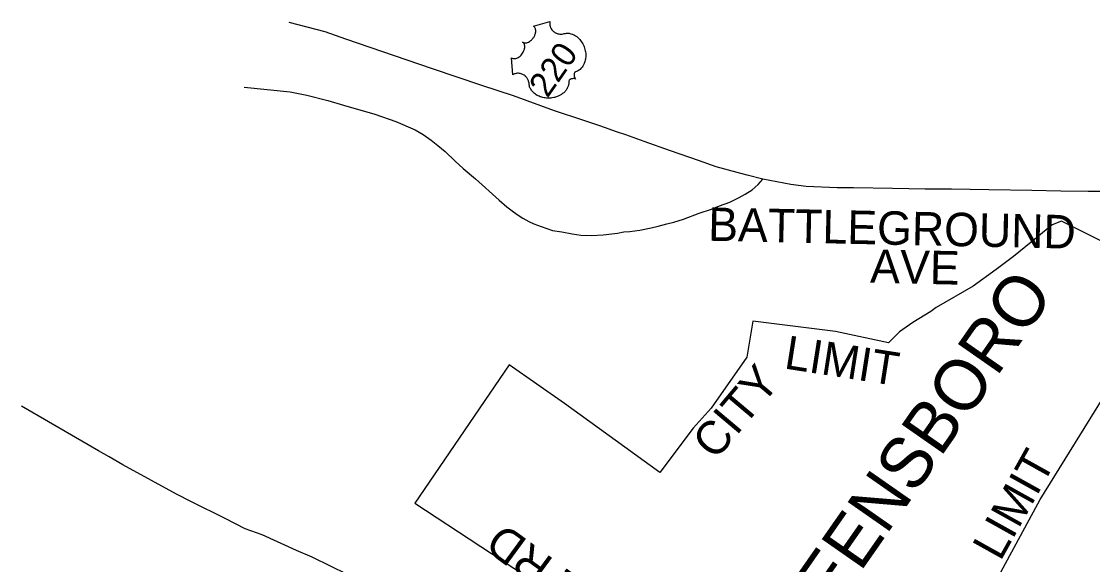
# Model space of a CAD drawing. Extents: x 1731327 to 1735374, y 884856 to 889832.
# Drawn here: x 1731417.3 to 1731582.7, y 885424.2 to 885508.1 of the extents above; entities that cross this region are included whole.
import ezdxf

# ---------------------------------------------------------------- set-up
doc = ezdxf.new("R2010")
doc.units = 0
for name, color, linetype in [('CTL Bench Mark CELL', 7, 'Continuous'), ('Exist Other Culture Located Object CELL', 7, 'Continuous'), ('Exist Other Culture Sign Text', 7, 'Continuous'), ('Exist Roads EOP Other Text', 7, 'Continuous'), ('Exist Roads EOP Text', 7, 'Continuous'), ('Exist Structure Major Deck Tunnel Box Culvert Text', 7, 'Continuous')]:
    doc.layers.add(name, color=color, linetype=linetype)

msp = doc.modelspace()

# ---------------------------------------------------------------- linework, layer by layer
at = {"layer": 'Exist Other Culture Located Object CELL'}
for points in [[(1731451.7, 885497.93), (1731458.83, 885497.21), (1731461.36, 885496.72), (1731464.62, 885495.89), (1731467.05, 885495.19), (1731471.9, 885493.78), (1731475.15, 885492.62), (1731478.1, 885491.36), (1731479.34, 885490.63), (1731480.59, 885489.77), (1731481.62, 885488.93), (1731482.74, 885487.99), (1731484.31, 885486.51)], [(1731484.31, 885486.51), (1731485.53, 885485.36), (1731487.42, 885483.77), (1731491.09, 885480.47), (1731492.28, 885479.45), (1731493.1, 885478.83), (1731493.87, 885478.28), (1731494.74, 885477.7), (1731495.69, 885477.2), (1731496.42, 885476.86), (1731497.57, 885476.4), (1731499.34, 885475.81), (1731500.77, 885475.58), (1731502.39, 885475.27), (1731503.68, 885475.08), (1731505.37, 885475.02), (1731507.16, 885475.15), (1731509.35, 885475.38), (1731510.36, 885475.58), (1731511.27, 885475.64), (1731512.81, 885475.87), (1731514.56, 885476.2), (1731515.67, 885476.47), (1731516.98, 885476.83), (1731518.09, 885477.11), (1731519.55, 885477.58), (1731521.98, 885478.49), (1731523.86, 885479.11), (1731525.1, 885479.62), (1731526.7, 885480.21), (1731528.18, 885480.88), (1731529.07, 885481.41), (1731530.14, 885482.08), (1731531.09, 885482.92), (1731531.83, 885483.76)], [(1731476.24, 885417.55), (1731472.57, 885419.98), (1731470.96, 885420.95), (1731469.44, 885421.77), (1731467.47, 885422.77), (1731465.14, 885423.93), (1731462.23, 885425.37), (1731459.79, 885426.39), (1731454.47, 885428.81), (1731451.85, 885429.73), (1731448.76, 885431.3), (1731443.57, 885433.89), (1731441.26, 885435.08), (1731437.37, 885437.2), (1731432.96, 885439.62), (1731430.84, 885440.83), (1731429.21, 885441.78), (1731417.3, 885448.65)]]:
    msp.add_lwpolyline(points, dxfattribs=at)
at = {"layer": 'Exist Other Culture Sign Text'}
for points in [[(1731585.56, 885473.42), (1731577.93, 885477.27), (1731576.52, 885476.67), (1731574.09, 885474.69), (1731570.52, 885471.77), (1731567.85, 885469.77), (1731564.28, 885467.19), (1731558.57, 885463.91), (1731557.76, 885463.3), (1731554.99, 885461.58), (1731552.93, 885460.13), (1731551.22, 885458.44), (1731543.04, 885460.22), (1731530.27, 885461.8), (1731529.35, 885456.25), (1731523.84, 885448.36), (1731521.03, 885445.29), (1731515.92, 885438.45), (1731501.19, 885449.07), (1731492.61, 885455.05), (1731478.04, 885433.68), (1731501.75, 885418.14)], [(1731436.56, 885269.4), (1731438.83, 885274.8), (1731441.07, 885273.73), (1731448, 885279.37), (1731458.75, 885273.36), (1731465.04, 885280.94), (1731460.35, 885284.21), (1731467.7, 885294.03), (1731466.12, 885347.48), (1731483.94, 885369.44), (1731489.63, 885375.45), (1731502.31, 885385.05), (1731500.42, 885387.96), (1731512.4, 885394.83), (1731516.87, 885391.9), (1731529.38, 885403.84), (1731536.47, 885399.16), (1731545.02, 885404.34), (1731554.34, 885410.44), (1731561.05, 885415.18), (1731565.57, 885417.53), (1731574.63, 885434.26), (1731585.3, 885451.43)]]:
    msp.add_lwpolyline(points, dxfattribs=at)
at = {"layer": 'Exist Roads EOP Other Text'}
for points in [[(1731504.02, 885492.85), (1731499.66, 885494.27), (1731493.29, 885496.6), (1731488.42, 885498.21), (1731480.78, 885500.78), (1731474.93, 885502.8), (1731467.42, 885505.34), (1731464.24, 885506.5), (1731458.67, 885507.93)], [(1731531.83, 885483.76), (1731529.38, 885484.36), (1731527.86, 885484.75), (1731524.59, 885485.66), (1731521.89, 885486.61), (1731517.57, 885488.12), (1731513.47, 885489.56), (1731510.65, 885490.58), (1731509.39, 885491), (1731506.65, 885491.96), (1731504.02, 885492.85)], [(1731594.82, 885480.03), (1731590.92, 885480.95), (1731588.57, 885481.48), (1731586.45, 885481.75), (1731584.48, 885481.83), (1731582.05, 885481.85), (1731577.86, 885481.9), (1731573.36, 885482), (1731566.72, 885482.1), (1731560.93, 885482.18), (1731556.89, 885482.2), (1731551.82, 885482.3), (1731545.82, 885482.38), (1731543.29, 885482.41), (1731538.5, 885482.62), (1731536.16, 885482.93), (1731531.83, 885483.76)]]:
    msp.add_lwpolyline(points, dxfattribs=at)
at = {"layer": 'Exist Roads EOP Text'}
for p, q in [((1731496.41, 885507.35), (1731498.94, 885508.1)), ((1731496.46, 885507.31), (1731496.41, 885507.35)), ((1731496.51, 885507.26), (1731496.46, 885507.31)), ((1731496.57, 885507.2), (1731496.51, 885507.26)), ((1731496.61, 885507.13), (1731496.57, 885507.2)), ((1731496.65, 885507.06), (1731496.61, 885507.13)), ((1731496.68, 885506.97), (1731496.65, 885507.06)), ((1731496.72, 885506.85), (1731496.68, 885506.97)), ((1731496.73, 885506.73), (1731496.72, 885506.85)), ((1731498.91, 885507.93), (1731498.9, 885507.83)), ((1731498.9, 885507.83), (1731498.91, 885507.65)), ((1731498.93, 885508.05), (1731498.91, 885507.93)), ((1731498.91, 885507.65), (1731498.92, 885507.57)), ((1731498.92, 885507.57), (1731498.93, 885507.49)), ((1731498.94, 885508.1), (1731498.93, 885508.05)), ((1731498.93, 885507.49), (1731498.95, 885507.41)), ((1731498.95, 885507.41), (1731498.96, 885507.33)), ((1731498.96, 885507.33), (1731499, 885507.24)), ((1731499, 885507.24), (1731499.04, 885507.14)), ((1731499.04, 885507.14), (1731499.08, 885507.05)), ((1731499.08, 885507.05), (1731499.12, 885506.97)), ((1731499.12, 885506.97), (1731499.22, 885506.82)), ((1731499.22, 885506.82), (1731499.29, 885506.74)), ((1731495.91, 885505.08), (1731496, 885505.15)), ((1731496, 885505.15), (1731496.08, 885505.23)), ((1731496.08, 885505.23), (1731496.16, 885505.3)), ((1731496.16, 885505.3), (1731496.23, 885505.39)), ((1731496.23, 885505.39), (1731496.31, 885505.47)), ((1731496.31, 885505.47), (1731496.36, 885505.55)), ((1731496.36, 885505.55), (1731496.42, 885505.64)), ((1731496.42, 885505.64), (1731496.48, 885505.73)), ((1731496.48, 885505.73), (1731496.53, 885505.82)), ((1731496.53, 885505.82), (1731496.58, 885505.93)), ((1731496.58, 885505.93), (1731496.62, 885506.02)), ((1731496.62, 885506.02), (1731496.66, 885506.14)), ((1731496.66, 885506.14), (1731496.69, 885506.26)), ((1731496.69, 885506.26), (1731496.71, 885506.36)), ((1731496.71, 885506.36), (1731496.73, 885506.51)), ((1731496.74, 885506.63), (1731496.73, 885506.73)), ((1731496.73, 885506.51), (1731496.74, 885506.63)), ((1731499.29, 885506.74), (1731499.36, 885506.67)), ((1731499.36, 885506.67), (1731499.49, 885506.55)), ((1731499.49, 885506.55), (1731499.56, 885506.49)), ((1731499.56, 885506.49), (1731499.63, 885506.44)), ((1731499.63, 885506.44), (1731499.71, 885506.39)), ((1731499.71, 885506.39), (1731499.79, 885506.35)), ((1731499.79, 885506.35), (1731499.87, 885506.31)), ((1731499.87, 885506.31), (1731499.95, 885506.28)), ((1731499.95, 885506.28), (1731500.04, 885506.24)), ((1731500.04, 885506.24), (1731500.16, 885506.2)), ((1731500.16, 885506.2), (1731500.28, 885506.18)), ((1731500.28, 885506.18), (1731500.48, 885506.15)), ((1731500.48, 885506.15), (1731500.7, 885506.15)), ((1731500.7, 885506.15), (1731500.83, 885506.16)), ((1731500.83, 885506.16), (1731500.95, 885506.18)), ((1731500.95, 885506.18), (1731501.11, 885506.22)), ((1731501.11, 885506.22), (1731501.2, 885506.24)), ((1731501.2, 885506.24), (1731501.31, 885506.26)), ((1731501.31, 885506.26), (1731501.51, 885506.28)), ((1731501.51, 885506.28), (1731501.6, 885506.29)), ((1731501.6, 885506.29), (1731501.7, 885506.28)), ((1731501.7, 885506.28), (1731501.79, 885506.28)), ((1731501.79, 885506.28), (1731501.89, 885506.27)), ((1731501.89, 885506.27), (1731501.98, 885506.26)), ((1731501.98, 885506.26), (1731502.16, 885506.21)), ((1731502.16, 885506.21), (1731502.34, 885506.16)), ((1731502.34, 885506.16), (1731502.42, 885506.13)), ((1731502.42, 885506.13), (1731502.61, 885506.04)), ((1731502.61, 885506.04), (1731502.7, 885506)), ((1731502.7, 885506), (1731502.88, 885505.9)), ((1731502.88, 885505.9), (1731503.07, 885505.76)), ((1731503.07, 885505.76), (1731503.25, 885505.61)), ((1731503.25, 885505.61), (1731503.44, 885505.43)), ((1731503.44, 885505.43), (1731503.55, 885505.31)), ((1731503.55, 885505.31), (1731503.67, 885505.16)), ((1731503.67, 885505.16), (1731503.77, 885505.02)), ((1731494.8, 885504.85), (1731494.71, 885504.92)), ((1731494.71, 885504.92), (1731494.8, 885504.87)), ((1731494.8, 885504.87), (1731494.85, 885504.84)), ((1731494.84, 885504.81), (1731494.8, 885504.85)), ((1731494.82, 885503.37), (1731494.92, 885503.59)), ((1731494.92, 885504.7), (1731494.84, 885504.81)), ((1731494.85, 885504.84), (1731494.91, 885504.82)), ((1731494.91, 885504.82), (1731494.97, 885504.81)), ((1731494.95, 885504.64), (1731494.92, 885504.7)), ((1731494.92, 885503.59), (1731494.96, 885503.69)), ((1731494.98, 885504.57), (1731494.95, 885504.64)), ((1731494.96, 885503.69), (1731494.99, 885503.82)), ((1731494.97, 885504.81), (1731495.07, 885504.79)), ((1731495.02, 885504.44), (1731494.98, 885504.57)), ((1731494.99, 885503.82), (1731495.02, 885503.94)), ((1731495.04, 885504.29), (1731495.02, 885504.44)), ((1731495.02, 885503.94), (1731495.04, 885504.08)), ((1731495.04, 885504.19), (1731495.04, 885504.29)), ((1731495.04, 885504.08), (1731495.04, 885504.19)), ((1731495.07, 885504.79), (1731495.16, 885504.79)), ((1731495.16, 885504.79), (1731495.3, 885504.8)), ((1731495.3, 885504.8), (1731495.38, 885504.82)), ((1731495.38, 885504.82), (1731495.44, 885504.84)), ((1731495.44, 885504.84), (1731495.6, 885504.9)), ((1731495.6, 885504.9), (1731495.77, 885504.99)), ((1731495.77, 885504.99), (1731495.84, 885505.03)), ((1731495.84, 885505.03), (1731495.91, 885505.08)), ((1731503.77, 885505.02), (1731503.91, 885504.81)), ((1731503.91, 885504.81), (1731504.01, 885504.64)), ((1731504.01, 885504.64), (1731504.11, 885504.44)), ((1731504.11, 885504.44), (1731504.16, 885504.31)), ((1731504.16, 885504.31), (1731504.22, 885504.16)), ((1731504.22, 885504.16), (1731504.28, 885503.99)), ((1731504.28, 885503.99), (1731504.34, 885503.79)), ((1731504.34, 885503.79), (1731504.39, 885503.57)), ((1731504.39, 885503.57), (1731504.42, 885503.4)), ((1731493.19, 885499.84), (1731493.02, 885502.49)), ((1731493.02, 885502.49), (1731493.09, 885502.44)), ((1731493.09, 885502.44), (1731493.19, 885502.4)), ((1731493.19, 885502.4), (1731493.24, 885502.38)), ((1731493.24, 885502.38), (1731493.35, 885502.37)), ((1731493.35, 885502.37), (1731493.49, 885502.36)), ((1731493.49, 885502.36), (1731493.65, 885502.39)), ((1731493.65, 885502.39), (1731493.81, 885502.43)), ((1731493.81, 885502.43), (1731493.9, 885502.47)), ((1731493.9, 885502.47), (1731494.04, 885502.54)), ((1731494.04, 885502.54), (1731494.19, 885502.63)), ((1731494.19, 885502.63), (1731494.33, 885502.75)), ((1731494.33, 885502.75), (1731494.47, 885502.88)), ((1731494.47, 885502.88), (1731494.6, 885503.03)), ((1731494.6, 885503.03), (1731494.71, 885503.19)), ((1731494.71, 885503.19), (1731494.82, 885503.37)), ((1731504.34, 885501.92), (1731504.23, 885501.62)), ((1731504.38, 885502.11), (1731504.34, 885501.92)), ((1731504.41, 885502.26), (1731504.38, 885502.11)), ((1731504.44, 885502.44), (1731504.41, 885502.26)), ((1731504.42, 885503.4), (1731504.45, 885503.18)), ((1731504.46, 885502.65), (1731504.44, 885502.44)), ((1731504.45, 885503.18), (1731504.46, 885503.06)), ((1731504.46, 885503.06), (1731504.46, 885502.88)), ((1731504.46, 885502.88), (1731504.46, 885502.65)), ((1731502.72, 885500.16), (1731502.69, 885500.08)), ((1731502.78, 885500.24), (1731502.72, 885500.16)), ((1731502.82, 885500.27), (1731502.78, 885500.24)), ((1731502.89, 885500.31), (1731502.82, 885500.27)), ((1731503.17, 885500.43), (1731502.89, 885500.31)), ((1731503.32, 885500.51), (1731503.17, 885500.43)), ((1731503.45, 885500.6), (1731503.32, 885500.51)), ((1731503.59, 885500.7), (1731503.45, 885500.6)), ((1731503.7, 885500.81), (1731503.59, 885500.7)), ((1731503.81, 885500.93), (1731503.7, 885500.81)), ((1731503.91, 885501.05), (1731503.81, 885500.93)), ((1731504, 885501.18), (1731503.91, 885501.05)), ((1731504.07, 885501.29), (1731504, 885501.18)), ((1731504.13, 885501.39), (1731504.07, 885501.29)), ((1731504.19, 885501.51), (1731504.13, 885501.39)), ((1731504.23, 885501.62), (1731504.19, 885501.51)), ((1731493.25, 885499.88), (1731493.19, 885499.84)), ((1731493.35, 885499.94), (1731493.25, 885499.88)), ((1731493.46, 885499.99), (1731493.35, 885499.94)), ((1731493.55, 885500.02), (1731493.46, 885499.99)), ((1731493.66, 885500.05), (1731493.55, 885500.02)), ((1731493.79, 885500.08), (1731493.66, 885500.05)), ((1731493.93, 885500.09), (1731493.79, 885500.08)), ((1731494.08, 885500.09), (1731493.93, 885500.09)), ((1731494.24, 885500.08), (1731494.08, 885500.09)), ((1731494.35, 885500.06), (1731494.24, 885500.08)), ((1731494.49, 885500.03), (1731494.35, 885500.06)), ((1731494.6, 885499.98), (1731494.49, 885500.03)), ((1731494.73, 885499.93), (1731494.6, 885499.98)), ((1731494.86, 885499.86), (1731494.73, 885499.93)), ((1731494.96, 885499.79), (1731494.86, 885499.86)), ((1731495.08, 885499.7), (1731494.96, 885499.79)), ((1731495.17, 885499.62), (1731495.08, 885499.7)), ((1731495.26, 885499.53), (1731495.17, 885499.62)), ((1731495.32, 885499.45), (1731495.26, 885499.53)), ((1731495.41, 885499.33), (1731495.32, 885499.45)), ((1731495.46, 885499.25), (1731495.41, 885499.33)), ((1731495.53, 885499.13), (1731495.46, 885499.25)), ((1731495.57, 885499.04), (1731495.53, 885499.13)), ((1731495.61, 885498.94), (1731495.57, 885499.04)), ((1731495.64, 885498.82), (1731495.61, 885498.94)), ((1731495.67, 885498.73), (1731495.64, 885498.82)), ((1731495.7, 885498.57), (1731495.67, 885498.73)), ((1731495.7, 885498.44), (1731495.7, 885498.57)), ((1731501.86, 885498.57), (1731501.84, 885498.44)), ((1731501.89, 885498.97), (1731501.86, 885498.9)), ((1731501.86, 885498.9), (1731501.86, 885498.79)), ((1731501.86, 885498.79), (1731501.86, 885498.68)), ((1731501.86, 885498.68), (1731501.86, 885498.57)), ((1731501.92, 885499.01), (1731501.89, 885498.97)), ((1731501.95, 885499.06), (1731501.92, 885499.01)), ((1731502.01, 885499.11), (1731501.95, 885499.06)), ((1731502.07, 885499.14), (1731502.01, 885499.11)), ((1731502.13, 885499.18), (1731502.07, 885499.14)), ((1731502.22, 885499.22), (1731502.13, 885499.18)), ((1731502.32, 885499.25), (1731502.22, 885499.22)), ((1731502.41, 885499.26), (1731502.32, 885499.25)), ((1731502.52, 885499.28), (1731502.41, 885499.26)), ((1731502.6, 885499.28), (1731502.52, 885499.28)), ((1731502.68, 885499.27), (1731502.6, 885499.28)), ((1731502.66, 885499.98), (1731502.65, 885499.91)), ((1731502.65, 885499.91), (1731502.65, 885499.82)), ((1731502.65, 885499.82), (1731502.66, 885499.75)), ((1731502.69, 885500.08), (1731502.66, 885499.98)), ((1731502.66, 885499.75), (1731502.67, 885499.65)), ((1731502.67, 885499.65), (1731502.69, 885499.58)), ((1731502.77, 885499.25), (1731502.68, 885499.27)), ((1731502.69, 885499.58), (1731502.7, 885499.52)), ((1731502.7, 885499.52), (1731502.76, 885499.4)), ((1731502.76, 885499.4), (1731502.79, 885499.34)), ((1731502.9, 885499.2), (1731502.77, 885499.25)), ((1731502.79, 885499.34), (1731502.83, 885499.28)), ((1731502.83, 885499.28), (1731502.9, 885499.2)), ((1731495.73, 885498.29), (1731495.7, 885498.44)), ((1731495.76, 885498.13), (1731495.73, 885498.29)), ((1731495.8, 885498.01), (1731495.76, 885498.13)), ((1731495.85, 885497.87), (1731495.8, 885498.01)), ((1731495.91, 885497.75), (1731495.85, 885497.87)), ((1731495.98, 885497.62), (1731495.91, 885497.75)), ((1731496.07, 885497.49), (1731495.98, 885497.62)), ((1731496.15, 885497.38), (1731496.07, 885497.49)), ((1731496.22, 885497.29), (1731496.15, 885497.38)), ((1731496.32, 885497.18), (1731496.22, 885497.29)), ((1731496.45, 885497.06), (1731496.32, 885497.18)), ((1731496.57, 885496.95), (1731496.45, 885497.06)), ((1731496.68, 885496.87), (1731496.57, 885496.95)), ((1731496.82, 885496.78), (1731496.68, 885496.87)), ((1731500.84, 885496.91), (1731500.71, 885496.82)), ((1731500.96, 885497), (1731500.84, 885496.91)), ((1731501.07, 885497.09), (1731500.96, 885497)), ((1731501.17, 885497.18), (1731501.07, 885497.09)), ((1731501.27, 885497.29), (1731501.17, 885497.18)), ((1731501.35, 885497.39), (1731501.27, 885497.29)), ((1731501.42, 885497.48), (1731501.35, 885497.39)), ((1731501.49, 885497.57), (1731501.42, 885497.48)), ((1731501.55, 885497.66), (1731501.49, 885497.57)), ((1731501.61, 885497.77), (1731501.55, 885497.66)), ((1731501.66, 885497.88), (1731501.61, 885497.77)), ((1731501.72, 885498), (1731501.66, 885497.88)), ((1731501.76, 885498.12), (1731501.72, 885498)), ((1731501.8, 885498.24), (1731501.76, 885498.12)), ((1731501.82, 885498.34), (1731501.8, 885498.24)), ((1731501.84, 885498.44), (1731501.82, 885498.34)), ((1731496.98, 885496.68), (1731496.82, 885496.78)), ((1731497.13, 885496.6), (1731496.98, 885496.68)), ((1731497.25, 885496.55), (1731497.13, 885496.6)), ((1731497.42, 885496.48), (1731497.25, 885496.55)), ((1731497.52, 885496.44), (1731497.42, 885496.48)), ((1731497.68, 885496.4), (1731497.52, 885496.44)), ((1731497.85, 885496.35), (1731497.68, 885496.4)), ((1731498.05, 885496.31), (1731497.85, 885496.35)), ((1731498.18, 885496.29), (1731498.05, 885496.31)), ((1731498.41, 885496.26), (1731498.18, 885496.29)), ((1731498.56, 885496.25), (1731498.41, 885496.26)), ((1731498.76, 885496.25), (1731498.56, 885496.25)), ((1731499.06, 885496.27), (1731498.76, 885496.25)), ((1731499.23, 885496.29), (1731499.06, 885496.27)), ((1731499.51, 885496.33), (1731499.23, 885496.29)), ((1731499.69, 885496.37), (1731499.51, 885496.33)), ((1731499.91, 885496.44), (1731499.69, 885496.37)), ((1731500.19, 885496.54), (1731499.91, 885496.44)), ((1731500.4, 885496.64), (1731500.19, 885496.54)), ((1731500.53, 885496.71), (1731500.4, 885496.64)), ((1731500.71, 885496.82), (1731500.53, 885496.71))]:
    msp.add_line(p, q, dxfattribs=at)

# ---------------------------------------------------------------- texts
at = {"layer": 'CTL Bench Mark CELL'}
msp.add_text('220', height=3.799, rotation=55.0911, dxfattribs=at).set_placement((1731498.55, 885496.16))
at = {"layer": 'Exist Structure Major Deck Tunnel Box Culvert Text'}
for s, height, rotation, p in [('BATTLEGROUND ', 5.163, 358.753, (1731523.33, 885474.23)), ('AVE', 5.163, 358.753, (1731548.35, 885467.74)), ('GREENSBORO', 7.852, 55.0911, (1731533.84, 885404.27)), ('LIMIT', 5.163, 351.0816, (1731534.96, 885454.52)), ('CITY', 5.163, 49.9369, (1731524.5, 885440.18)), ('LIMIT', 5.163, 60.8945, (1731568.5, 885424.6)), ('PLEASANT RIDGE RD', 5.163, 143.8218, (1731549.57, 885388.45))]:
    msp.add_text(s, height=height, rotation=rotation, dxfattribs=at).set_placement(p)

doc.saveas('drawing.dxf')
